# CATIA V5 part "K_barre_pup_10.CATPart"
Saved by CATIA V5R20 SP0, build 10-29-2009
Part number: barre_pup_10
Bounding box of the stored display mesh (mm): x -70.846 to -67.931, y 45.144 to 191.141, z -108.013 to -92.262
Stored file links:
  G:\Khaled_CFAO_2011\ST2M\ST2M_GR2\gcausse\Khaled\CAD_ThinkMotion\K_barre_pup_10.CATPart
  C:\Documents and Settings\gcausse\Bureau\video thinkmotio\assemblage_gcausse\pupitre_think.CATProduct
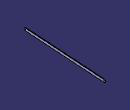
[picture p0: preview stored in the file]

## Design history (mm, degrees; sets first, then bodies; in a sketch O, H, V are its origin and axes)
Set1
  Sketch1 on Plane1, origin (-55.7229, 0, 6.855), H (0, 1, 0), V (0.1221, 0, 0.9925)
    line L1 (47.8269, -99.987) -> (188.8382, -110.7486)
    arc A1 centre (188.6479, -113.2413) radius 2.5 from (188.8382, -110.7486) to (188.4577, -115.7341) cw
    point P3 (188.6479, -113.2413)
    line L2 (188.4577, -115.7341) -> (47.4464, -104.9725)
    arc A2 centre (47.6366, -102.4797) radius 2.5 from (47.4464, -104.9725) to (47.8269, -99.987) cw
    point P6 (47.6366, -102.4797)
    reference projected point E1 (188.6479, -113.2413) from Point1
    reference projected line E2 (188.6479, -113.2413) -> (47.6366, -102.4797) from Line1
    reference projected point E3 (47.6366, -102.4797) from Point2
    distance L1 L2 = 5
    tangency: A1 L1, L2 A1, A2 L1, A2 L2
    coincidence: P3 E1, P6 E3
    parallelism: L1 E2
Set2
  Plane1: linked copy from another document
  Point1: linked copy from another document
  Line1: linked copy from another document
  Point2: linked copy from another document
Body1 (main body)
  Pad1: profile Sketch1, direction (0.9925, 0, -0.1221), length -1
  Sketch2 on end face of Pad1, origin (-69.4866, 56.2831, -96.8374), H (0.1221, 0, 0.9925), V (0, 1, 0)
    point P1 (2.1174, -8.6465)
    reference projected point E1 (2.1174, -8.6465) from Point2
    coincidence: P1 E1
  Hole1: placed by Sketch2, at (-69.2281, 47.6366, -94.7359) direction (0.9925, 0, -0.1221), diameter 1, depth 1
  Sketch3 on end face of Pad1, origin (-69.4323, 56.089, -96.3963), H (0.1221, 0, 0.9925), V (0, 1, 0)
    point P1 (-9.0887, 132.5589)
    reference projected point E1 (-9.0887, 132.5589) from Point1
    coincidence: P1 E1
  Hole2: placed by Sketch3, at (-70.542, 188.6479, -105.4169) direction (0.9925, 0, -0.1221), diameter 1, depth 1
